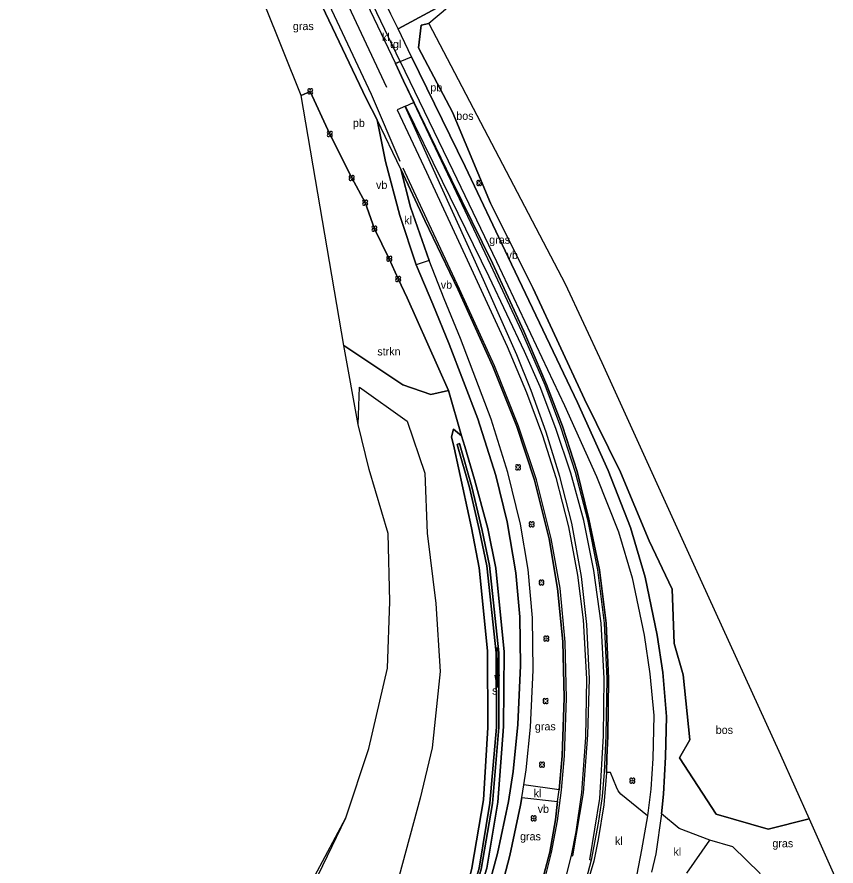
# Model space of a CAD drawing. Extents: x 154825 to 158680, y 370717 to 378075.
# Drawn here: x 157898.7 to 158001, y 372485.5 to 372591.5 of the extents above; entities that cross this region are included whole.
import ezdxf

# ---------------------------------------------------------------- set-up
doc = ezdxf.new("R2010")
doc.units = 0
for name, color, linetype in [('blokstreep', 7, 'Continuous'), ('boom', 7, 'Continuous'), ('bos(vs)', 7, 'Continuous'), ('cultuurscheiding', 7, 'Continuous'), ('deelstreep(1-1)', 7, 'Continuous'), ('deelstreep(9-3)', 7, 'Continuous'), ('grazige vegetatie(vs)', 7, 'Continuous'), ('hoogteverschillijn', 7, 'Continuous'), ('insteek sloot', 7, 'Continuous'), ('kantstreep', 7, 'Continuous'), ('klinkerverharding(vs)', 7, 'Continuous'), ('maaiveldlijn algemeen - gesloten verharding', 7, 'Continuous'), ('maaiveldlijn algemeen - onverhard', 7, 'Continuous'), ('maaiveldlijn algemeen - open verharding', 7, 'Continuous'), ('maaiveldlijn algemeen - tegelverharding', 7, 'Continuous'), ('naambord', 7, 'Continuous'), ('raster - hek', 7, 'Continuous'), ('Sloot bodem', 7, 'Continuous'), ('sloot(vs)', 7, 'Continuous'), ('stroomrichting  watergangen', 7, 'Continuous'), ('struiken(vs)', 7, 'Continuous'), ('tegelverh(vs)', 7, 'Continuous'), ('verkeersb_z kabel', 7, 'Continuous'), ('vlak_akkerland', 7, 'Continuous'), ('vlak_Bos', 7, 'Continuous'), ('vlak_Grazige_vegetatie', 7, 'Continuous'), ('vlak_Struiken', 7, 'Continuous')]:
    doc.layers.add(name, color=color, linetype=linetype)

msp = doc.modelspace()

# ---------------------------------------------------------------- linework, layer by layer
at = {"layer": 'blokstreep'}
for points in [[(157947.22, 372580.38), (157948.21, 372580.85)], [(157947.22, 372580.38), (157946.19, 372579.92)], [(157967.9, 372486.8), (157968.09, 372486.75), (157969.42, 372494.64), (157969.97, 372501.88), (157970.17, 372508.88), (157969.87, 372515.64), (157969.2, 372521.66), (157968, 372528.31), (157966.5, 372534.15), (157964.76, 372539.68), (157962.9, 372544.88), (157961.1, 372549.32), (157956.95, 372558.71), (157951.48, 372570.79), (157947.18, 372580.35)], [(157970.22, 372486.27), (157971.49, 372493.91), (157971.94, 372501.75), (157972.01, 372508.9), (157971.63, 372515.8), (157970.73, 372522.41), (157969.46, 372528.63), (157967.86, 372534.54), (157966, 372540.11), (157964.01, 372545.32), (157962.06, 372549.76), (157957.66, 372559.05), (157951.84, 372570.98), (157947.22, 372580.38)]]:
    msp.add_lwpolyline(points, dxfattribs=at)
at = {"layer": 'boom'}
for centre in [(157935.33, 372582.22), (157937.77, 372576.9), (157940.5, 372571.41), (157956.42, 372570.78), (157942.18, 372568.34), (157943.34, 372565.07), (157945.19, 372561.33), (157946.3, 372558.81), (157961.27, 372535.29), (157962.96, 372528.16), (157964.2, 372520.9), (157964.8, 372513.9), (157964.7, 372506.08), (157964.25, 372498.16), (157975.54, 372496.15), (157963.22, 372491.45)]:
    msp.add_circle(centre, 0.006, dxfattribs=at)
for centre, start, end in [((157935.17, 372582.38), 357.075, 272.925), ((157935.17, 372582.06), 87.075, 2.925), ((157935.48, 372582.38), 267.075, 182.925), ((157935.48, 372582.06), 177.075, 92.925), ((157937.61, 372577.06), 357.075, 272.925), ((157937.61, 372576.74), 87.075, 2.925), ((157937.93, 372577.06), 267.075, 182.925), ((157937.93, 372576.74), 177.075, 92.925), ((157940.34, 372571.57), 357.075, 272.925), ((157940.34, 372571.25), 87.075, 2.925), ((157940.66, 372571.57), 267.075, 182.925), ((157940.66, 372571.25), 177.075, 92.925), ((157956.26, 372570.94), 357.075, 272.925), ((157956.57, 372570.94), 267.075, 182.925), ((157956.26, 372570.63), 87.075, 2.925), ((157956.57, 372570.63), 177.075, 92.925), ((157942.02, 372568.5), 357.075, 272.925), ((157942.02, 372568.18), 87.075, 2.925), ((157942.34, 372568.5), 267.075, 182.925), ((157942.34, 372568.18), 177.075, 92.925), ((157943.18, 372565.23), 357.075, 272.925), ((157943.18, 372564.92), 87.075, 2.925), ((157943.5, 372565.23), 267.075, 182.925), ((157943.5, 372564.92), 177.075, 92.925), ((157945.03, 372561.48), 357.075, 272.925), ((157945.35, 372561.48), 267.075, 182.925), ((157945.03, 372561.17), 87.075, 2.925), ((157945.35, 372561.17), 177.075, 92.925), ((157946.14, 372558.97), 357.075, 272.925), ((157946.14, 372558.65), 87.075, 2.925), ((157946.46, 372558.97), 267.075, 182.925), ((157946.46, 372558.65), 177.075, 92.925), ((157961.12, 372535.44), 357.075, 272.925), ((157961.12, 372535.13), 87.075, 2.925), ((157961.43, 372535.44), 267.075, 182.925), ((157961.43, 372535.13), 177.075, 92.925), ((157962.8, 372528.32), 357.075, 272.925), ((157962.8, 372528), 87.075, 2.925), ((157963.12, 372528.32), 267.075, 182.925), ((157963.12, 372528), 177.075, 92.925), ((157964.04, 372521.05), 357.075, 272.925), ((157964.35, 372521.05), 267.075, 182.925), ((157964.04, 372520.74), 87.075, 2.925), ((157964.35, 372520.74), 177.075, 92.925), ((157964.64, 372514.06), 357.075, 272.925), ((157964.64, 372513.74), 87.075, 2.925), ((157964.96, 372514.06), 267.075, 182.925), ((157964.96, 372513.74), 177.075, 92.925), ((157964.54, 372506.24), 357.075, 272.925), ((157964.86, 372506.24), 267.075, 182.925), ((157964.54, 372505.93), 87.075, 2.925), ((157964.86, 372505.93), 177.075, 92.925), ((157964.09, 372498.31), 357.075, 272.925), ((157964.09, 372498), 87.075, 2.925), ((157964.41, 372498.31), 267.075, 182.925), ((157964.41, 372498), 177.075, 92.925), ((157975.38, 372496.3), 357.075, 272.925), ((157975.38, 372495.99), 87.075, 2.925), ((157975.7, 372496.3), 267.075, 182.925), ((157975.7, 372495.99), 177.075, 92.925), ((157963.07, 372491.6), 357.075, 272.925), ((157963.38, 372491.6), 267.075, 182.925), ((157963.07, 372491.29), 87.075, 2.925), ((157963.38, 372491.29), 177.075, 92.925)]:
    msp.add_arc(centre, 0.158, start, end, dxfattribs=at)
at = {"layer": 'bos(vs)'}
msp.add_lwpolyline([(157950.11, 372590.7), (157949.19, 372590.51), (157948.86, 372587.67), (157953.09, 372579.64), (157957.84, 372568.28), (157963.15, 372557.59), (157969.55, 372543.8), (157974.07, 372534.69), (157977.63, 372526.11), (157980.52, 372520.08), (157980.75, 372513.29), (157981.87, 372509.35), (157982.72, 372501.26), (157981.44, 372499.01), (157986.02, 372491.97), (157992.49, 372490.1), (157997.63, 372491.37)], dxfattribs=at)
at = {"layer": 'cultuurscheiding'}
msp.add_lwpolyline([(157952.58, 372544.86), (157954.19, 372539.22)], dxfattribs=at)
at = {"layer": 'deelstreep(1-1)'}
for points in [[(157946.55, 372573.48), (157942.97, 372581.83), (157934.4, 372600.09), (157925.63, 372618.55), (157921.74, 372626.73)], [(157937.61, 372598.22), (157944.85, 372582.74)]]:
    msp.add_lwpolyline(points, dxfattribs=at)
at = {"layer": 'deelstreep(9-3)'}
for points in [[(157946.19, 372579.92), (157949.82, 372572.12), (157954.9, 372561.21), (157959.89, 372550.38), (157962.31, 372544.64), (157964.3, 372539.27), (157965.99, 372533.99), (157967.57, 372527.87), (157968.71, 372521.81), (157969.41, 372516.22), (157969.82, 372508.86), (157969.67, 372501.55), (157969.17, 372494.66), (157968.49, 372489.76), (157967.9, 372486.8)], [(157967.9, 372486.8), (157966.4, 372480.87), (157964.14, 372473.83), (157961.28, 372466.81), (157959.13, 372462.23), (157955.73, 372456.1), (157951.58, 372449.77), (157947.51, 372444.57), (157943.17, 372439.56), (157938.03, 372434.28), (157932.88, 372429.26), (157917.8, 372414.96), (157900.57, 372398.73)]]:
    msp.add_lwpolyline(points, dxfattribs=at)
at = {"layer": 'hoogteverschillijn'}
msp.add_lwpolyline([(157935.2, 372482.04), (157939.78, 372491.5), (157942.62, 372500.18), (157944.97, 372510.2), (157945.25, 372518.52), (157945.04, 372527.03), (157942.66, 372535), (157941.31, 372540.61), (157941.48, 372545.27), (157947.41, 372541.03), (157949.62, 372534.57), (157949.91, 372527.04), (157950.99, 372518.26), (157951.53, 372509.79), (157950.55, 372500.25), (157949.06, 372493.97), (157946.43, 372484.27)], dxfattribs=at)
at = {"layer": 'insteek sloot'}
for points in [[(157954.19, 372539.22), (157953.23, 372540.06), (157952.94, 372539.09), (157953.29, 372537.7), (157955.47, 372527.74), (157956.42, 372522.74), (157957.47, 372512.36), (157957.5, 372502.78), (157956.95, 372493.75), (157955.48, 372485.23), (157954.2, 372480.04), (157953.67, 372478.63)], [(157953.67, 372478.63), (157954.1, 372478.2), (157954.97, 372478.04), (157955.3, 372478.66), (157957.37, 372485.22), (157958.74, 372493.47), (157959.47, 372502.93), (157959.54, 372512.25), (157958.49, 372522.7), (157957.48, 372527.63), (157955.84, 372533.76), (157954.62, 372537.88), (157954.19, 372539.22)]]:
    msp.add_lwpolyline(points, dxfattribs=at)
at = {"layer": 'kantstreep'}
for points in [[(157947.03, 372583.33), (157952.82, 372571.15), (157957.83, 372560.57), (157961.69, 372552.29), (157964.61, 372545.57), (157966.57, 372540.32), (157968.39, 372534.69), (157969.94, 372528.75), (157971.19, 372522.48), (157972.03, 372515.82), (157972.35, 372508.89), (157972.24, 372501.74), (157972.02, 372497.2), (157971.75, 372494.17), (157971.29, 372490.83), (157970.4, 372486.24)], [(157964.06, 372481.67), (157965.46, 372487.18), (157966.21, 372491.14), (157966.68, 372494.96), (157967.05, 372499.26), (157967.31, 372506.45), (157967.17, 372513.46), (157966.51, 372520.18), (157965.41, 372526.39), (157963.57, 372533.71), (157961.34, 372540.43), (157958.34, 372547.96), (157953.94, 372557.53), (157949.88, 372566.26), (157946.94, 372572.62)], [(157970.4, 372486.24), (157968.71, 372479.75), (157966.29, 372472.47), (157963.29, 372465.06), (157959.47, 372457.49), (157955.04, 372450.45), (157950.31, 372444.14), (157945.19, 372438.22), (157939.88, 372432.7), (157935.68, 372428.65), (157919.64, 372413.43), (157902.02, 372396.85), (157893.16, 372388.45), (157875.35, 372371.69), (157863.62, 372360.57), (157853.07, 372350.36), (157843.79, 372341.19), (157832.37, 372329.62), (157817.57, 372314.15), (157804.62, 372300.14)], [(157970.4, 372486.24), (157970.22, 372486.27)]]:
    msp.add_lwpolyline(points, dxfattribs=at)
at = {"layer": 'maaiveldlijn algemeen - gesloten verharding'}
for points in [[(157925.51, 372629.01), (157933.72, 372611.4), (157939.18, 372599.96), (157945.96, 372585.69)], [(157943.67, 372578.67), (157942.32, 372581.35), (157933.46, 372599.99), (157924.43, 372618.76), (157920.54, 372626.8)], [(157946.56, 372585.96), (157947.95, 372586.54)], [(157946.56, 372585.96), (157953.12, 372572.33), (157958.57, 372561), (157967.07, 372543.02), (157971.06, 372534.14), (157973.8, 372527.22), (157975.5, 372521.49), (157977, 372514.32), (157977.72, 372509.5), (157978.21, 372504.27), (157978.1, 372498.92), (157977.86, 372495.07), (157977.42, 372491.75)], [(157947.95, 372586.54), (157954.65, 372572.84), (157960.05, 372561.53), (157968.68, 372543.38), (157972.5, 372534.9), (157975.3, 372527.75), (157977.13, 372521.57), (157978.65, 372514.31), (157979.34, 372509.66), (157979.8, 372504.16), (157979.66, 372499.11), (157979.42, 372494.46), (157979.19, 372492.02)], [(157945.96, 372585.69), (157946.97, 372583.56), (157952.94, 372571.18), (157958.06, 372560.76), (157961.97, 372552.3), (157964.83, 372545.64), (157966.83, 372540.44), (157968.65, 372534.74), (157970.12, 372528.82), (157971.43, 372522.5), (157972.26, 372515.84), (157972.58, 372508.91), (157972.48, 372501.69), (157972.37, 372499.04), (157972.32, 372497.17)], [(157946.64, 372572.5), (157943.67, 372578.67)], [(157966.4, 372495.02), (157966.78, 372499.24), (157967.03, 372506.49), (157966.84, 372513.54), (157966.19, 372520.15), (157965.14, 372526.34), (157963.34, 372533.68), (157961.12, 372540.37), (157958.1, 372547.87), (157953.8, 372557.43), (157949.65, 372566.12), (157946.64, 372572.5)], [(157950.17, 372561.12), (157948.56, 372560.55)], [(157956.96, 372480.62), (157958.72, 372487.07), (157960.08, 372493.56), (157960.67, 372497.29), (157961.26, 372503.17), (157961.57, 372510.54), (157961.49, 372516.6), (157960.99, 372522.12), (157959.91, 372528.46), (157958.5, 372534.25), (157956.23, 372541.33), (157952.67, 372550.64), (157950.64, 372555.66), (157948.56, 372560.55)], [(157961.74, 372494.05), (157962, 372495.65), (157962.3, 372497.5), (157962.81, 372502.82), (157963.14, 372509.93), (157963.08, 372516.5), (157962.54, 372522.51), (157961.59, 372528.17), (157960, 372534.64), (157957.93, 372541.3), (157954.1, 372551.35), (157952.04, 372556.32), (157950.17, 372561.12)], [(157972.32, 372497.17), (157971.97, 372493.12), (157971.27, 372488.8), (157970.71, 372486.1), (157969.53, 372482.06)], [(157864.5, 372368.13), (157869.15, 372372.56), (157886.25, 372388.63), (157895.13, 372397.07), (157898.79, 372400.56), (157916.39, 372417.15), (157931.13, 372431.24), (157936.35, 372436.39), (157941.12, 372441.4), (157945.09, 372446.03), (157949.21, 372451.3), (157952.94, 372456.85), (157956.1, 372462.48), (157958.74, 372467.86), (157961.57, 372474.9), (157963.8, 372481.74), (157965.22, 372487.24), (157965.93, 372491.28), (157966.21, 372493.54), (157966.4, 372495.02)], [(157961.74, 372494.05), (157961.59, 372493.11), (157960.26, 372486.82), (157958.48, 372480.12), (157956.3, 372473.66), (157953.33, 372466.9), (157950.22, 372460.87), (157946.65, 372455.09), (157942.95, 372449.98), (157942.75, 372449.44), (157939.41, 372445.41), (157938.84, 372445.13), (157935.6, 372441.6), (157925.35, 372431.65), (157910.36, 372417.43), (157897.25, 372404.98), (157896.96, 372404.48), (157893.44, 372401.18), (157892.88, 372400.89), (157876.85, 372385.69), (157860.57, 372370.22), (157860.56, 372369.75)], [(157977.42, 372491.75), (157976.7, 372487.51), (157976.08, 372484.46)], [(157979.19, 372492.02), (157978.45, 372487.03), (157977.91, 372484.74)]]:
    msp.add_lwpolyline(points, dxfattribs=at)
at = {"layer": 'maaiveldlijn algemeen - onverhard'}
msp.add_lwpolyline([(157998.41, 372471.76), (157995.2, 372477.35), (157992.51, 372482.51), (157991.46, 372484.61), (157988.08, 372487.9), (157985.23, 372488.72)], dxfattribs=at)
at = {"layer": 'maaiveldlijn algemeen - open verharding'}
for points in [[(157954.79, 372594.65), (157946.31, 372590.02)], [(157948.56, 372560.55), (157946.49, 372566.74), (157944.74, 372573.47), (157943.67, 372578.67)], [(157946.64, 372572.5), (157947.83, 372567.77), (157950.17, 372561.12)], [(157977.42, 372491.75), (157974.11, 372494.47), (157973.78, 372494.87), (157973.56, 372495.32), (157972.8, 372497.18), (157972.32, 372497.17)], [(157966.4, 372495.02), (157962, 372495.65)], [(157961.74, 372494.05), (157966.21, 372493.54)], [(157985.23, 372488.72), (157981.38, 372490.18), (157979.19, 372492.02)], [(157982.36, 372484.59), (157985.23, 372488.72)]]:
    msp.add_lwpolyline(points, dxfattribs=at)
at = {"layer": 'maaiveldlijn algemeen - tegelverharding'}
for points in [[(157946.56, 372585.96), (157941.74, 372596.07), (157936.12, 372607.89), (157931.6, 372617.51), (157926.18, 372629.1), (157923.2, 372635.59), (157921.45, 372639.8), (157919.93, 372643.75), (157917.41, 372650.53)], [(157946.31, 372590.02), (157945.39, 372591.88), (157944.48, 372593.81)], [(157947.95, 372586.54), (157946.31, 372590.02)], [(157946.56, 372585.96), (157945.96, 372585.69)]]:
    msp.add_lwpolyline(points, dxfattribs=at)
at = {"layer": 'raster - hek'}
for points in [[(157950.11, 372590.7), (157967.13, 372558.2), (157971.74, 372548.37), (157984, 372521.34), (157994.03, 372499.37), (157997.63, 372491.37)], [(157935.33, 372582.22), (157937.77, 372576.9), (157940.5, 372571.41), (157942.18, 372568.34), (157943.34, 372565.07), (157945.19, 372561.33), (157946.3, 372558.81)], [(157997.63, 372491.37), (158000.96, 372483.91)]]:
    msp.add_lwpolyline(points, dxfattribs=at)
at = {"layer": 'Sloot bodem'}
msp.add_lwpolyline([(157954.75, 372478.44), (157954.37, 372478.65), (157954.65, 372479.67), (157954.88, 372479.84), (157956.41, 372485.22), (157957.76, 372493.33), (157958.58, 372502.83), (157958.53, 372512.12), (157957.37, 372522.98), (157956.44, 372527.35), (157955.19, 372532.77), (157953.65, 372538.14), (157953.96, 372538.26), (157955.48, 372532.84), (157956.79, 372527.41), (157957.7, 372523.02), (157958.86, 372512.11), (157958.88, 372502.81), (157958.09, 372493.3), (157956.68, 372485.12), (157955.17, 372479.73), (157955.1, 372479.5), (157954.75, 372478.44)], dxfattribs=at)
at = {"layer": 'stroomrichting  watergangen'}
for p, q in [((157958.63, 372512.77), (157958.7, 372507.77)), ((157958.7, 372507.77), (157958.4, 372509.33)), ((157958.72, 372507.79), (157958.97, 372509.35))]:
    msp.add_line(p, q, dxfattribs=at)
at = {"layer": 'struiken(vs)'}
for points in [[(157946.3, 372558.81), (157947.41, 372556.44), (157951.23, 372547.96), (157952.58, 372544.86)], [(157952.58, 372544.86), (157950.4, 372544.39), (157946.87, 372545.59), (157939.52, 372550.48)]]:
    msp.add_lwpolyline(points, dxfattribs=at)
at = {"layer": 'tegelverh(vs)'}
msp.add_lwpolyline([(157934.19, 372581.7), (157935.33, 372582.22)], dxfattribs=at)
at = {"layer": 'vlak_akkerland'}
msp.add_lwpolyline([(157932.04, 372477.01), (157939.78, 372491.5), (157942.62, 372500.18), (157944.97, 372510.2), (157945.25, 372518.52), (157945.04, 372527.03), (157942.66, 372535), (157941.31, 372540.61), (157939.52, 372550.48), (157946.87, 372545.59), (157950.4, 372544.39), (157952.58, 372544.86), (157954.19, 372539.22), (157953.23, 372540.06), (157952.94, 372539.09), (157953.29, 372537.7), (157955.47, 372527.74), (157956.42, 372522.74), (157957.47, 372512.36), (157957.5, 372502.78), (157956.95, 372493.75), (157955.48, 372485.23)], dxfattribs=at)
at = {"layer": 'vlak_Bos'}
msp.add_lwpolyline([(157997.63, 372491.37), (157992.49, 372490.1), (157986.02, 372491.97), (157981.44, 372499.01), (157982.72, 372501.26), (157981.87, 372509.35), (157980.75, 372513.29), (157980.52, 372520.08), (157977.63, 372526.11), (157974.07, 372534.69), (157969.55, 372543.8), (157963.15, 372557.59), (157957.84, 372568.28), (157953.09, 372579.64), (157948.86, 372587.67), (157949.19, 372590.51), (157950.11, 372590.7), (157967.13, 372558.2), (157971.74, 372548.37), (157984, 372521.34), (157994.03, 372499.37)], close=True, dxfattribs=at)
at = {"layer": 'vlak_Grazige_vegetatie'}
for points in [[(157933.46, 372599.99), (157942.32, 372581.35), (157943.67, 372578.67), (157944.74, 372573.47), (157946.49, 372566.74), (157948.56, 372560.55), (157950.64, 372555.66), (157952.67, 372550.64), (157956.23, 372541.33), (157958.5, 372534.25), (157959.91, 372528.46), (157960.99, 372522.12), (157961.49, 372516.6), (157961.57, 372510.54), (157961.26, 372503.17), (157960.67, 372497.29), (157960.08, 372493.56), (157958.72, 372487.07), (157956.96, 372480.62)], [(157957.37, 372485.22), (157958.74, 372493.47), (157959.47, 372502.93), (157959.54, 372512.25), (157958.49, 372522.7), (157957.48, 372527.63), (157955.84, 372533.76), (157954.62, 372537.88), (157954.19, 372539.22), (157952.58, 372544.86), (157951.23, 372547.96), (157947.41, 372556.44), (157946.3, 372558.81), (157945.19, 372561.33), (157943.34, 372565.07), (157942.18, 372568.34), (157940.5, 372571.41), (157937.77, 372576.9), (157935.33, 372582.22), (157934.19, 372581.7), (157927.34, 372598.87)], [(157991.46, 372484.61), (157988.08, 372487.9), (157985.23, 372488.72), (157981.38, 372490.18), (157979.19, 372492.02), (157979.42, 372494.46), (157979.66, 372499.11), (157979.8, 372504.16), (157979.34, 372509.66), (157978.65, 372514.31), (157977.13, 372521.57), (157975.3, 372527.75), (157972.5, 372534.9), (157968.68, 372543.38), (157960.05, 372561.53), (157954.65, 372572.84), (157947.95, 372586.54), (157946.31, 372590.02), (157954.79, 372594.65), (157950.11, 372590.7), (157949.19, 372590.51), (157948.86, 372587.67), (157953.09, 372579.64), (157957.84, 372568.28), (157963.15, 372557.59), (157969.55, 372543.8), (157974.07, 372534.69), (157977.63, 372526.11), (157980.52, 372520.08), (157980.75, 372513.29), (157981.87, 372509.35), (157982.72, 372501.26), (157981.44, 372499.01), (157986.02, 372491.97), (157992.49, 372490.1), (157997.63, 372491.37), (158000.96, 372483.91)], [(157958.48, 372480.12), (157960.26, 372486.82), (157961.59, 372493.11), (157961.74, 372494.05), (157966.21, 372493.54), (157965.93, 372491.28), (157965.22, 372487.24), (157963.8, 372481.74)]]:
    msp.add_lwpolyline(points, dxfattribs=at)
for points in [[(157978.1, 372498.92), (157977.86, 372495.07), (157977.42, 372491.75), (157974.11, 372494.47), (157973.78, 372494.87), (157973.56, 372495.32), (157972.8, 372497.18), (157972.32, 372497.17), (157972.37, 372499.04), (157972.48, 372501.69), (157972.58, 372508.91), (157972.26, 372515.84), (157971.43, 372522.5), (157970.12, 372528.82), (157968.65, 372534.74), (157966.83, 372540.44), (157964.83, 372545.64), (157961.97, 372552.3), (157958.06, 372560.76), (157952.94, 372571.18), (157946.97, 372583.56), (157945.96, 372585.69), (157946.56, 372585.96), (157953.12, 372572.33), (157958.57, 372561), (157967.07, 372543.02), (157971.06, 372534.14), (157973.8, 372527.22), (157975.5, 372521.49), (157977, 372514.32), (157977.72, 372509.5), (157978.21, 372504.27)], [(157966.78, 372499.24), (157966.4, 372495.02), (157962, 372495.65), (157962.3, 372497.5), (157962.81, 372502.82), (157963.14, 372509.93), (157963.08, 372516.5), (157962.54, 372522.51), (157961.59, 372528.17), (157960, 372534.64), (157957.93, 372541.3), (157954.1, 372551.35), (157952.04, 372556.32), (157950.17, 372561.12), (157947.83, 372567.77), (157946.64, 372572.5), (157949.65, 372566.12), (157953.8, 372557.43), (157958.1, 372547.87), (157961.12, 372540.37), (157963.34, 372533.68), (157965.14, 372526.34), (157966.19, 372520.15), (157966.84, 372513.54), (157967.03, 372506.49)], [(157954.19, 372539.22), (157954.62, 372537.88), (157955.84, 372533.76), (157957.48, 372527.63), (157958.49, 372522.7), (157959.54, 372512.25), (157959.47, 372502.93), (157958.74, 372493.47), (157957.37, 372485.22), (157955.3, 372478.66), (157954.97, 372478.04), (157954.1, 372478.2), (157953.67, 372478.63), (157954.2, 372480.04), (157955.48, 372485.23), (157956.95, 372493.75), (157957.5, 372502.78), (157957.47, 372512.36), (157956.42, 372522.74), (157955.47, 372527.74), (157953.29, 372537.7), (157952.94, 372539.09), (157953.23, 372540.06)], [(157954.37, 372478.65), (157954.75, 372478.44), (157955.1, 372479.5), (157955.17, 372479.73), (157956.68, 372485.12), (157958.09, 372493.3), (157958.88, 372502.81), (157958.86, 372512.11), (157957.7, 372523.02), (157956.79, 372527.41), (157955.48, 372532.84), (157953.96, 372538.26), (157953.65, 372538.14), (157955.19, 372532.77), (157956.44, 372527.35), (157957.37, 372522.98), (157958.53, 372512.12), (157958.58, 372502.83), (157957.76, 372493.33), (157956.41, 372485.22), (157954.88, 372479.84), (157954.65, 372479.67)]]:
    msp.add_lwpolyline(points, close=True, dxfattribs=at)
at = {"layer": 'vlak_Struiken'}
msp.add_lwpolyline([(157952.58, 372544.86), (157950.4, 372544.39), (157946.87, 372545.59), (157939.52, 372550.48), (157934.19, 372581.7), (157935.33, 372582.22), (157937.77, 372576.9), (157940.5, 372571.41), (157942.18, 372568.34), (157943.34, 372565.07), (157945.19, 372561.33), (157946.3, 372558.81), (157947.41, 372556.44), (157951.23, 372547.96)], close=True, dxfattribs=at)

# ---------------------------------------------------------------- texts
at = {"layer": 'bos(vs)'}
for p in [(157953.56, 372578.67), (157985.95, 372501.99)]:
    msp.add_text('bos', height=1, dxfattribs=at).set_placement(p)
at = {"layer": 'grazige vegetatie(vs)'}
for p in [(157933.16, 372589.88), (157957.67, 372563.2), (157963.37, 372502.43), (157961.52, 372488.7), (157993.02, 372487.83)]:
    msp.add_text('gras', height=1, dxfattribs=at).set_placement(p)
at = {"layer": 'klinkerverharding(vs)'}
for p in [(157944.27, 372588.5), (157947.05, 372565.64), (157963.22, 372494.08), (157973.38, 372488.13), (157980.67, 372486.79)]:
    msp.add_text('kl', height=1, dxfattribs=at).set_placement(p)
at = {"layer": 'naambord'}
for p in [(157950.32, 372582.22), (157940.65, 372577.78)]:
    msp.add_text('pb', height=1, dxfattribs=at).set_placement(p)
at = {"layer": 'sloot(vs)'}
msp.add_text('sl', height=1, dxfattribs=at).set_placement((157958.03, 372506.9))
at = {"layer": 'struiken(vs)'}
msp.add_text('strkn', height=1, dxfattribs=at).set_placement((157943.7, 372549.25))
at = {"layer": 'tegelverh(vs)'}
msp.add_text('tgl', height=1, dxfattribs=at).set_placement((157945.28, 372587.63))
at = {"layer": 'verkeersb_z kabel'}
for p in [(157943.54, 372570.04), (157959.84, 372561.3), (157951.62, 372557.58), (157963.72, 372492.13)]:
    msp.add_text('vb', height=1, dxfattribs=at).set_placement(p)

doc.saveas('drawing.dxf')
